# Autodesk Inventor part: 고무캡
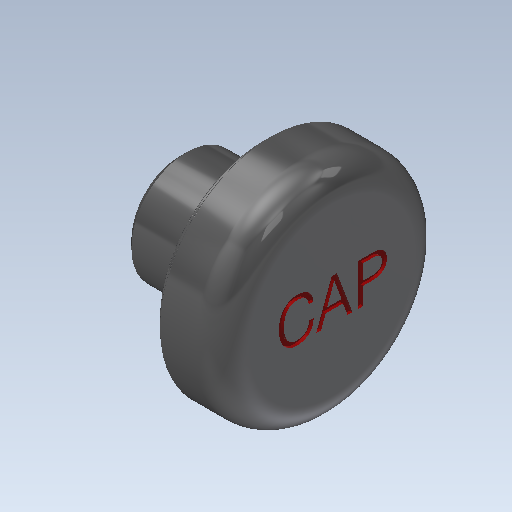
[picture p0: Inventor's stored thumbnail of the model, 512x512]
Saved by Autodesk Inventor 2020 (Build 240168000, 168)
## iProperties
Created: 2017-06
Part Number: 고무캡
Material: 고무
Document SubType Name: Modeling
Designer: mduedu
Density: 1 g/cm^3
Appearance: 고무 - 검은색 - 버전 1.1
Author: mduedu
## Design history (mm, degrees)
sketch "스케치1"
  geometry: L1 (0, 0)-(11, 0); L2 (11, 0)-(11, 8); L3 (11, 8)-(6.5, 8); L4 (0, 4)-(0, 0); L5 (0, 4)-(6, 4); L6 (6, 4)-(6, 7.5); L7 (6, 7.5)-(6.5, 7.5); L8 (6.5, 7.5)-(6.5, 8)
  constraints: 16 end point, 2 horizontal, 2 parallel, 2 perpendicular, 2 point on line, 1 vertical
  dimensions: "d0" = 16 diameter of L3 L1; "d2" = 8 diameter of L5 L1; "d6" = 5 distance between parallel lines of L2 L6; "d7" = 0.5 distance between parallel lines of L8 L6; "d8" = 15 diameter of L7 L1; "d9" = 6 distance between parallel lines of L6 L4
revolve "회전1" sketch "스케치1" stored, may be unused: angle "d10" = 90 deg
hole "구멍1" diameter "d22" = 5; stored, may be unused: countersink angle "d26" = 90 deg, drill point angle "d28" = 0 deg; dims "d23" = 6, "d24" = 4, "d25" = 2, "d27" = 6, "d30" = 10, "d31" = 10
chamfer "모따기1" distance "d13" = 0.5; stored, may be unused: second distance "d14" = 2, angle "d15" = 45 deg
fillet "모깎기3" dims "d29" = 1
fillet "모깎기1" dims "d16" = 0.1
fillet "모깎기2" dims "d17" = 2
sketch "스케치3"
  geometry: 2 further points
  constraints: 1 coincident, 1 other
feature "엠보싱1" sketch "스케치3" dims "d16" = 0.1, "d18" = 0.2, "d19" = 0
node "솔리드1"
